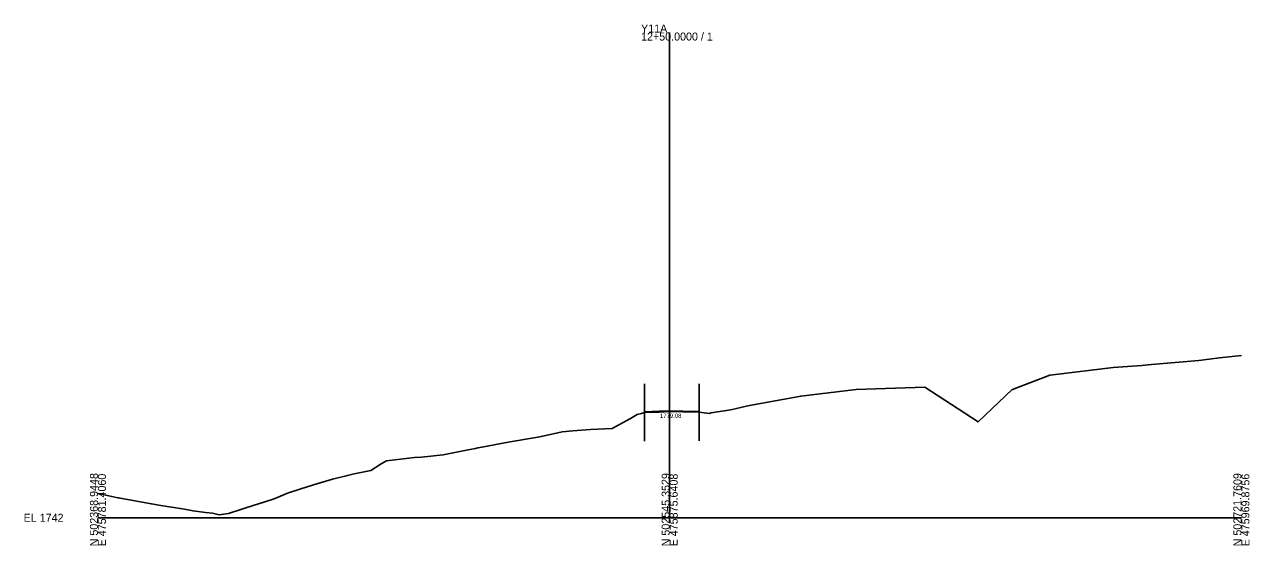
# Model space of a CAD drawing. Extents: x -26 to 403, y -10 to 5098.
# Drawn here: x -25.7 to 402.8, y 2490.3 to 2672.4 of the extents above; entities that cross this region are included whole.
import ezdxf

# ---------------------------------------------------------------- set-up
doc = ezdxf.new("R2010")
doc.units = 0
for name, color, linetype in [('Exist Cross Section Cell', 7, 'Continuous'), ('Exist XS Center Line Elevation Label', 7, 'Continuous'), ('Exist XS Ground Line', 7, 'Continuous'), ('Prop XS Finish Grade Pavement', 7, 'Continuous'), ('Scratch_Level_5', 7, 'Continuous')]:
    doc.layers.add(name, color=color, linetype=linetype)

msp = doc.modelspace()

# ---------------------------------------------------------------- linework, layer by layer
at = {"layer": 'Exist Cross Section Cell'}
for p, q in [((200, 2500), (200, 2669.58)), ((0, 2500), (200, 2500)), ((200, 2500), (400, 2500))]:
    msp.add_line(p, q, dxfattribs=at)
at = {"layer": 'Exist XS Ground Line'}
msp.add_lwpolyline([(0, 2508.46), (0.67, 2508.34), (6.92, 2506.99), (7.36, 2506.9), (7.77, 2506.82), (18.7, 2504.82), (22.02, 2504.29), (30.25, 2502.96), (33.26, 2502.37), (37.61, 2501.83), (40.05, 2501.65), (42.44, 2500.99), (45.65, 2501.47), (54.96, 2504.47), (55.5, 2504.59), (61.64, 2506.63), (63.83, 2507.59), (66.36, 2508.59), (70.68, 2509.99), (75.4, 2511.54), (82.07, 2513.5), (86.87, 2514.61), (89.67, 2515.36), (95.52, 2516.49), (99.04, 2518.8), (100.99, 2519.91), (108.79, 2520.79), (110.71, 2521.01), (113.14, 2521.15), (120.75, 2521.98), (129.49, 2523.72), (132.09, 2524.24), (132.88, 2524.42), (134.34, 2524.65), (143.52, 2526.36), (153.87, 2528.17), (155.06, 2528.4), (155.59, 2528.52), (162.45, 2529.99), (166.11, 2530.42), (172.35, 2530.82), (179.92, 2531.21), (186.33, 2534.69), (188.69, 2536.03), (190.1, 2536.47), (191.17, 2536.81), (196.32, 2536.95), (199.92, 2537.08), (204.56, 2536.98), (210.31, 2536.84), (212.04, 2536.7), (213.88, 2536.48), (214.42, 2536.62), (221.38, 2537.75), (227.37, 2539.08), (245.84, 2542.54), (265.23, 2544.8), (289.32, 2545.61), (307.88, 2533.49), (319.77, 2544.8), (320.07, 2544.81), (320.56, 2545.01), (332.96, 2549.8), (333.99, 2549.94), (355.11, 2552.51), (365.21, 2553.26), (368.56, 2553.51), (385.06, 2554.99), (392.33, 2555.9), (400, 2556.72)], dxfattribs=at)
at = {"layer": 'Prop XS Finish Grade Pavement'}
for p, q in [((191.18, 2537.06), (191.18, 2536.81)), ((210.31, 2537.09), (210.31, 2536.84))]:
    msp.add_line(p, q, dxfattribs=at)
msp.add_lwpolyline([(191.18, 2537.06), (196.31, 2537.2), (199.92, 2537.33), (204.57, 2537.23), (210.31, 2537.09)], dxfattribs=at)
at = {"layer": 'Scratch_Level_5'}
for p, q in [((191.18, 2546.81), (191.18, 2526.81)), ((210.31, 2546.85), (210.31, 2526.85))]:
    msp.add_line(p, q, dxfattribs=at)

# ---------------------------------------------------------------- texts
at = {"layer": 'Exist Cross Section Cell'}
for s, p in [('Y11A', (190, 2669.58)), ('12+50.0000 / 1', (190, 2666.78)), ('EL 1742', (-26, 2498.6))]:
    msp.add_text(s, height=2.8, dxfattribs=at).set_placement(p)
for s, p in [('N 502368.9448', (0, 2490)), ('E 475781.4060', (2.8, 2490)), ('N 502545.3529', (200, 2490)), ('E 475875.6408', (202.8, 2490)), ('N 502721.7609', (400, 2490)), ('E 475969.8756', (402.8, 2490))]:
    msp.add_text(s, height=2.8, rotation=90, dxfattribs=at).set_placement(p)
at = {"layer": 'Exist XS Center Line Elevation Label'}
msp.add_text('1779.08', height=1.5, dxfattribs=at).set_placement((196.62, 2534.9))

doc.saveas('drawing.dxf')
